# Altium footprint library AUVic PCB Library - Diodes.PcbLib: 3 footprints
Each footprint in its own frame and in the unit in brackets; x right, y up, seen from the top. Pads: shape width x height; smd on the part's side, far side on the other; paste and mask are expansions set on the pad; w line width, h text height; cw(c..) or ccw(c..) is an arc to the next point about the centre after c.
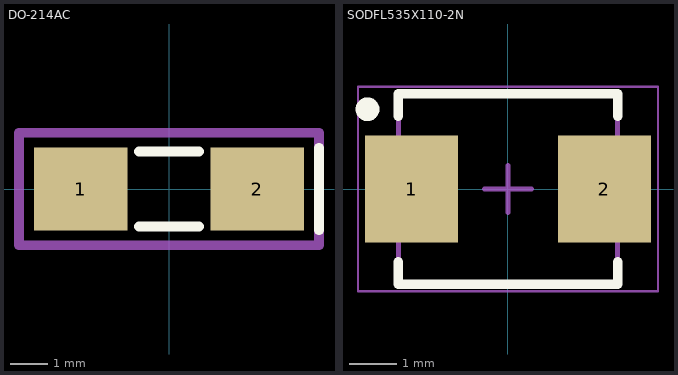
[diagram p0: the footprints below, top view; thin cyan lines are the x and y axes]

## *_ [mm]

## DO-214AC [mm]
pads (2):
  rect 2.5x2.2 smd: 1(-2.35,0) 2(2.35,0)
Top Overlay:
  lines w0.254: -0.8,-1 0.8,-1 ; -0.8,1 0.8,1 ; 4,-1.1 4,1.1
Mechanical 15:
  lines w0.254: -4,-1.5 4,-1.5 4,1.5 -4,1.5 -4,-1.5

## SODFL535X110-2N [mm] "SODFL, 2-Leads, Body 3.63x5.35mm, IPC Medium Density"
height 1.1
pads (2):
  rect 1.95x2.25 smd: 1(-2.025,0) 2(2.025,0)
Top Overlay:
  circle w0.25: c-2.95,1.675 r0.125
  lines w0.2: -2.3,-1.525 -2.3,-2 2.3,-2 2.3,-1.525 ; -2.3,1.525 -2.3,2 2.3,2 2.3,1.525
Mechanical 13:
  lines w0.1: -2.3,-1.975 2.3,-1.975 2.3,1.975 -2.3,1.975 -2.3,-1.975
Mechanical 15:
  lines w0.05: -3.15,-2.15 3.15,-2.15 3.15,2.15 -3.15,2.15 -3.15,-2.15
  lines w0.1: -0.5,0 0.5,0 ; 0,-0.5 0,0.5
3D body: height 1.1, standoff 0, extent -2.3,-1.975 2.3,1.975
